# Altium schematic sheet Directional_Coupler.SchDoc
size A4; SheetNumber: 1; SheetTotal: 1
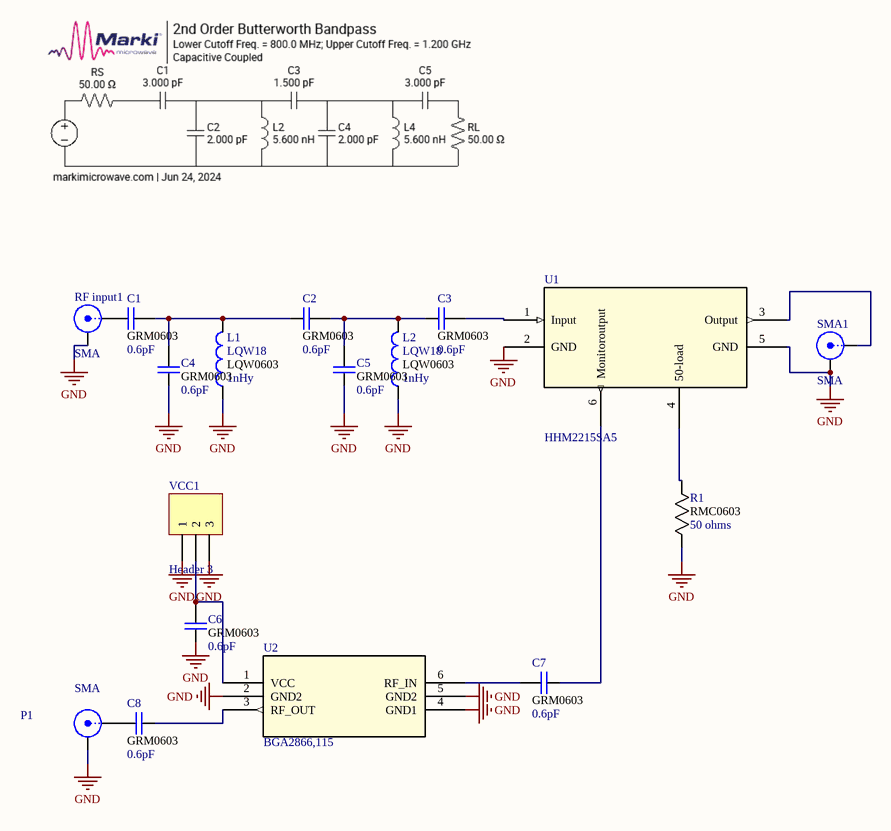
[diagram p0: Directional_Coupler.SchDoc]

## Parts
C1  value 0.6pF  footprint: GRM0603  [CAPC1608X90N]  (hidden comment: Cap 0603)
C2  value 0.6pF  footprint: GRM0603  [CAPC1608X90N]  (hidden comment: Cap 0603)
C3  value 0.6pF  footprint: GRM0603  [CAPC1608X90N]  (hidden comment: Cap 0603)
C4  value 0.6pF  footprint: GRM0603  [CAPC1608X90N]  (hidden comment: Cap 0603)
C5  value 0.6pF  footprint: GRM0603  [CAPC1608X90N]  (hidden comment: Cap 0603)
C6  value 0.6pF  footprint: GRM0603  [CAPC1608X90N]  (hidden comment: Cap 0603)
C7  value 0.6pF  footprint: GRM0603  [CAPC1608X90N]  (hidden comment: Cap 0603)
C8  value 0.6pF  footprint: GRM0603  [CAPC1608X90N]  (hidden comment: Cap 0603)
L1  LQW18  value 1nHy  Parameter 1: LQW0603  [INDC1608X100N]
L2  LQW18  value 1nHy  Parameter 1: LQW0603  [INDC1608X100N]
P1  SMA  [SMA-142-0701-851_V2]
R1  value 50 ohms  footprint: RMC0603  [RESC1508X55N]  (hidden comment: Resistor)
RF_input1  SMA  [SMA-142-0701-851_V2]
SMA1  SMA  [SMA-142-0701-851_V2]
U1  HHM2215SA5  [HHM-6_1P6X0P8]
U2  BGA2866,115  [SOT363_NXP]
VCC1  Header 3  [HDR1X3]

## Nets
GND: C4.1 C5.1 C6.1 L1.1 L2.1 P1.2(Y) R1.1 RF_input1.2(Y) SMA1.2(Y) U1.2(GND) U1.5(GND) U2.2(GND2) U2.4(GND1) U2.5(GND2) VCC1.1 VCC1.3
NetC1_1: C1.1 RF_input1.1(X)
NetC1_2: C1.2 C2.1 C4.2 L1.2
NetC2_2: C2.2 C3.1 C5.2 L2.2
NetC3_2: C3.2 U1.1(Input)
NetC6_2: C6.2 U2.1(VCC) VCC1.2
NetC7_1: C7.1 U1.6(Monitoroutput)
NetC7_2: C7.2 U2.6(RF_IN)
NetC8_1: C8.1 U2.3(RF_OUT)
NetC8_2: C8.2 P1.1(X)
NetR1_2: R1.2 U1.4(50-load)
NetSMA1_1: SMA1.1(X) U1.3(Output)

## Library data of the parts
C1-C8 = Cap: Capacitor GRM18 0603
L1 L2 = LQW18: Ind RF Chip Wirewound 18nH 5% 100MHz 40Q-Factor 550mA 0603 Paper T/R; MP: LQW18AN18NJ00D
P1 = SMB: SMB Straight Connector
R1 = Resistor: Resistor RMC0603; Mfr_Name: Stackpole International
RF_input1 SMA1 = SMA: SMA Straight Connector
U1 = HHM2215SA5: No Description Available; Mfr_Name: TDK
U2 = BGA2866,115: No Description Available; Mfr_Name: NXP
VCC1 = Header 3: Header, 3-Pin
